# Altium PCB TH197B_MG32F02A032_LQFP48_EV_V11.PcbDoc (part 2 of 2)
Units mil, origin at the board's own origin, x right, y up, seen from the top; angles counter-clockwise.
Board outline 4094.49 x 2637.8 mil, 2 copper layers (Top Layer, Bottom Layer); 114 components, 111 nets, 502 pads, 245 vias.
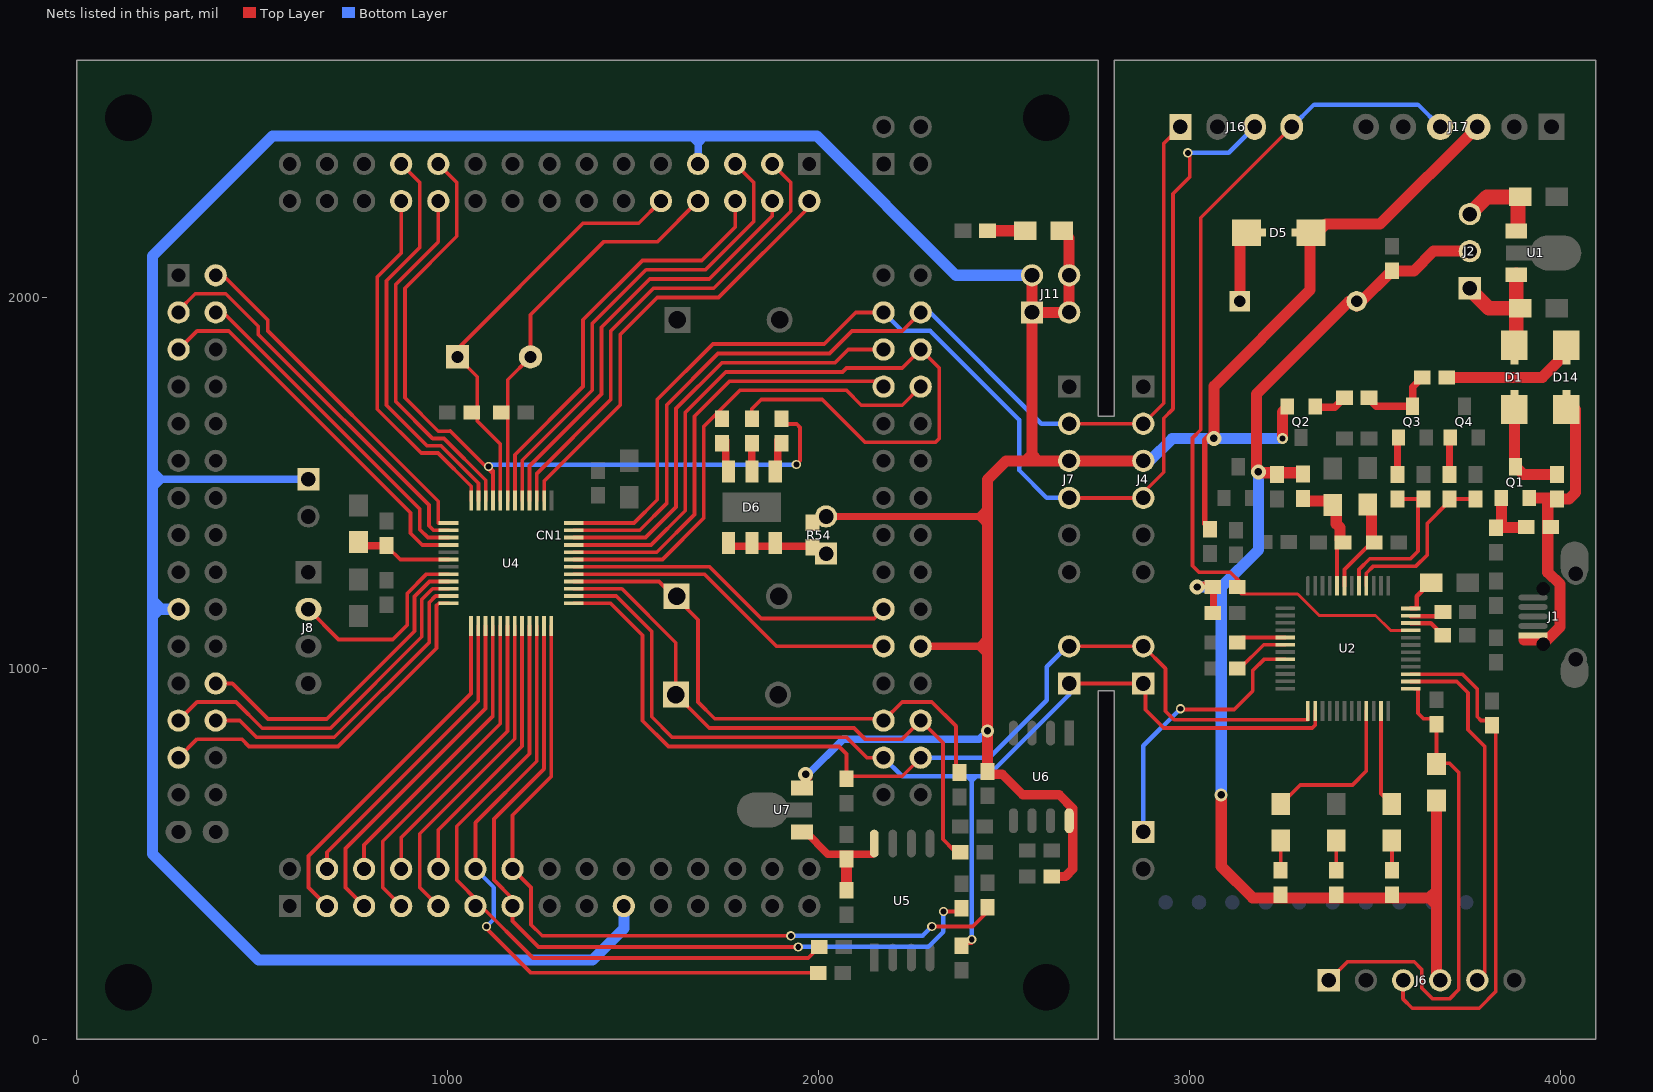
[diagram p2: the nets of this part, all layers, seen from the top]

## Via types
v1: diameter 30, hole 12, Top Layer to Bottom Layer, tented both sides, 93 vias
v2: diameter 20, hole 12, Top Layer to Bottom Layer, tented both sides, 89 vias
v3: diameter 25, hole 12, Top Layer to Bottom Layer, tented both sides, 32 vias
v4: diameter 25, hole 16, Top Layer to Bottom Layer, tented both sides, 21 vias
v5: diameter 40, hole 20, Top Layer to Bottom Layer, tented both sides, 4 vias
v6: diameter 30, hole 16, Top Layer to Bottom Layer, tented both sides, 3 vias
v7: diameter 35, hole 20, Top Layer to Bottom Layer, tented both sides, 2 vias
v8: diameter 50, hole 12, Top Layer to Bottom Layer, tented both sides, 1 vias

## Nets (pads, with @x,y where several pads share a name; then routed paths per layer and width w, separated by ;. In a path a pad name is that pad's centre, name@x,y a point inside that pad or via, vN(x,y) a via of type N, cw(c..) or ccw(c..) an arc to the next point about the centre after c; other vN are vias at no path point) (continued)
ICP/SWD_SDA: J16.4 J17.4 R13.2 U2.33 | length 2401.6
  Top Layer w8: R13.2@3138.04,1199.74 3291.04,1199.74 3349.04,1141.74 3501.04,1141.74 3540.94,1101.84 U2.33@3595.5,1101.84
  Top Layer w10: R13.2@3138.04,1218.74 3138.04,1229.74 3109.04,1258.74 3025.04,1258.74 3007.79,1275.99 3007.79,1620.49 3030.04,1642.74 3030.04,2213.74 J16.4@3275.04,2458.74
  Bottom Layer w12: J16.4@3275.04,2458.74 3335.04,2518.74 3615.04,2518.74 J17.4@3675.04,2458.74
MG_PA0: CN1.114 U4.45 | length 929.8
  Top Layer w10: CN1.114@375.04,958.74 420.04,958.74 515.79,862.99 674.29,862.99 ; 620.04,862.99 674.29,862.99 ; U4.45@1002.56,1233.74 951.52,1233.74 910.98,1193.2 910.98,1099.69 674.29,862.99
MG_PA1: CN1.115 U4.46 | length 1056.6
  Top Layer w10: CN1.115@275.04,858.74 325.04,908.74 430.04,908.74 500.54,838.24 684.54,838.24 ; 620.04,838.24 684.54,838.24 ; U4.46@1002.56,1214.06 959.68,1214.05 930.67,1185.05 930.67,1084.37 684.54,838.24
MG_PA2: CN1.116 U4.47 | length 941.9
  Top Layer w10: CN1.116@375.04,858.74 440.04,858.74 485.29,813.49 694.79,813.49 ; 620.04,813.49 694.79,813.49 ; U4.47@1002.56,1194.37 967.83,1194.37 950.35,1176.89 950.35,1069.06 694.79,813.49
MG_PA3: CN1.117 U4.48 | length 1068.7
  Top Layer w10: CN1.117@275.04,758.74 325.04,808.74 445.04,808.74 465.04,788.74 705.04,788.74 ; 620.04,788.74 705.04,788.74 ; U4.48@1002.56,1174.68 975.98,1174.68 970.04,1168.74 970.04,1053.74 705.04,788.74
MG_PA8: CN1.3 U4.1 | length 957.1
  Top Layer w10: CN1.3@675.04,358.74 625.04,408.74 625.04,493.74 1063.03,931.73 U4.1@1063.03,1113.71
MG_PA9: CN1.4 U4.2 | length 823.8
  Top Layer w10: CN1.4@675.04,458.74 675.04,503.74 1082.72,911.42 U4.2@1082.72,1113.71
MG_PA10: CN1.5 U4.3 | length 932
  Top Layer w10: CN1.5@775.04,358.74 725.04,408.74 725.04,513.74 1102.4,891.1 U4.3@1102.4,1113.71
MG_PA11: CN1.6 U4.4 | length 800.8
  Top Layer w10: CN1.6@775.04,458.74 775.04,523.74 1122.09,870.79 ; 1122.09,868.74 1122.09,870.79 ; U4.4@1122.09,1113.71 1122.09,870.79
MG_PA12: CN1.7 U4.5 | length 916.9
  Top Layer w10: CN1.7@875.04,358.74 825.04,408.74 825.04,533.74 1141.77,850.47 1141.77,878.74 ; 1141.77,868.74 1141.77,878.74 ; U4.5@1141.77,1113.71 1141.77,878.74
MG_PA13: CN1.8 U4.6 | length 773.6
  Top Layer w10: CN1.8@875.04,458.74 875.04,543.74 1161.46,830.16 U4.6@1161.46,1113.71
MG_PA14: CN1.9 U4.7 | length 881.8
  Top Layer w10: CN1.9@975.04,358.74 925.04,408.74 925.04,553.74 1181.14,809.84 U4.7@1181.14,1113.71
MG_PA15: CN1.10 U4.8 | length 748.5
  Top Layer w10: CN1.10@975.04,458.74 975.04,563.74 1200.83,789.53 U4.8@1200.83,1113.71
MG_PB0: CN1.11 R48.1 U4.9 | length 1867.4
  Top Layer w10: CN1.11@1080.04,368.74 1082.54,366.24 1230.04,218.74 1972.04,218.74 R48.1@2002.04,248.74 ; CN1.11@1085.04,368.74 1025.04,428.74 1025.04,573.74 1220.51,769.21 1220.51,888.74 ; 1220.51,868.74 1220.51,888.74 ; U4.9@1220.51,1113.71 1220.51,888.74
MG_PB1: CN1.12 R52.1 U4.10 | length 1876.1
  Top Layer w10: CN1.12@1075.04,458.74 1075.04,583.74 1240.2,748.9 1240.2,888.74 ; v4(1105.04,303.74) 1105.04,298.74 1225.04,178.74 R52.1@1999.04,178.74 ; 1240.2,868.74 1240.2,888.74 ; U4.10@1240.2,1113.71 1240.2,888.74
  Bottom Layer w12: CN1.12@1075.04,458.74 1125.04,408.74 1125.04,323.74 v4(1105.04,303.74)
MG_PB2: CN1.13 R49.1 U4.11 | length 2166.9
  Top Layer w10: CN1.13@1175.04,358.74 1175.04,318.74 1245.04,248.74 v4(1945.04,248.74) ; CN1.13@1175.04,378.74 1125.04,428.74 1125.04,593.74 1259.88,728.58 U4.11@1259.88,1113.71 ; v4(2336.31,344.01) R49.1@2385.04,344.01
  Top Layer w12: R49.1@2385.04,344.01 R49.1@2390.31,344.01
  Bottom Layer w12: v4(1945.04,248.74) 2295.04,248.74 2336.31,290.01 v4(2336.31,344.01)
MG_PB3: CN1.14 R50.1 U4.12 | length 2170.3
  Top Layer w10: CN1.14@1175.04,438.74 CN1.14@1175.04,458.74 ; U4.12@1279.57,1113.71 1279.57,708.27 1175.04,603.74 CN1.14@1175.04,458.74 ; v4(1925.04,278.74) 1255.04,278.74 1225.04,308.74 1225.04,408.74 CN1.14@1175.04,458.74 ; v4(2305.04,303.74) 2415.04,303.74 2455.04,343.74 R50.1@2455.04,355.74
  Bottom Layer w12: v4(1925.04,278.74) 2280.04,278.74 v4(2305.04,303.74)
MG_PB8(TX): CN1.33 J5.2 J15.2 R51.1 U2.13 U4.13 | length 2956.1
  Top Layer w10: U4.13@1340.04,1174.68 1439.09,1174.69 1525.29,1088.49 1525.29,858.49 1595.04,788.74 2055.04,788.74 2075.04,768.74 R51.1@2075.04,708.74 ; R51.1@2075.04,701.74 R51.1@2075.04,708.74 ; CN1.33@2275.04,758.74 2225.04,708.74 R51.1@2075.04,708.74 ; J15.2@2675.04,1058.74 J5.2@2875.04,1058.74 2935.04,998.74 2935.04,883.74 2958.04,860.74 ; 3195.04,860.74 2958.04,860.74 ; U2.13@3318.49,884.39 3318.49,860.74 2958.04,860.74
  Bottom Layer w12: CN1.33@2275.04,758.74 2460.04,758.74 2615.04,913.74 2615.04,1003.74 2670.04,1058.74 J15.2@2675.04,1058.74
MG_PB9(RX): CN1.34 J5.1 J15.1 R53.1 U2.14 U4.14 | length 3078.5
  Top Layer w10: U4.14@1340.04,1194.37 1454.41,1194.37 1550.04,1098.74 1550.04,868.74 1605.04,813.74 2075.04,813.74 2130.04,758.74 CN1.34@2175.04,758.74 ; R53.1@2393.04,258.74 v4@2412.6,258.74 ; J15.1@2675.04,958.74 J5.1@2875.04,958.74 2880.81,952.97 2880.81,887.97 2930.04,838.74 3330.04,838.74 3338.18,846.88 U2.14@3338.18,884.39
  Bottom Layer w12: CN1.34@2175.04,758.74 2225.04,708.74 2400.2,708.74 ; v4(2412.6,268.74) 2412.6,696.34 ; J15.1@2675.04,958.74 2675.04,928.74 2455.04,708.74 2425,708.74 ; 2400.2,708.74 2412.6,708.74 ; 2400.2,708.74 2412.6,696.34 ; 2412.6,696.34 2425,708.74 ; 2412.6,696.34 2412.6,708.74 ; 2412.6,708.74 2425,708.74
MG_PB10: CN1.35 R47.1 SW3.1 U4.15 | length 1595.7
  Top Layer w10: U4.15@1340.04,1214.06 1469.72,1214.06 1615.04,1068.74 SW3.1@1615.04,928.74 1705.04,838.74 2095.04,838.74 2125.04,808.74 2225.04,808.74 CN1.35@2275.04,858.74 ; CN1.35@2285.04,848.74 2335.04,798.74 2335.04,538.74 2365.04,508.74 R47.1@2382.04,508.74
MG_PB11: CN1.36 R46.1 SW4.1 U4.16 | length 1531.9
  Top Layer w10: U4.16@1340.04,1233.74 1570.04,1233.74 SW4.1@1613.64,1190.14 ; SW4.1@1597.24,1208.44 1614.59,1191.09 1675.04,1130.64 1675.04,908.74 1720.04,863.74 2170.04,863.74 CN1.36@2175.04,858.74 2225.04,908.74 2305.04,908.74 2370.04,843.74 2370.04,718.74 R46.1@2370.04,703.74 ; SW4.1@1617.24,1188.74 SW4.1@1617.24,1193.74
MG_PB13: CN1.40 U4.17 | length 915.6
  Top Layer w10: U4.17@1340.04,1253.43 1691.85,1253.43 1886.54,1058.74 CN1.40@2175.04,1058.74
MG_PB14: CN1.42 U4.18 | length 903.1
  Top Layer w10: U4.18@1340.04,1273.11 1705.67,1273.11 1845.04,1133.74 2150.04,1133.74 CN1.42@2175.04,1158.74
MG_PC0: CN1.53 R28.1 U4.19 | length 1360.8
  Top Layer w10: U4.19@1340.04,1292.8 1579.09,1292.8 1690.04,1403.74 1690.04,1650.67 1725.57,1686.2 1788.11,1748.74 1870.04,1748.74 ; 1925.04,1748.74 1870.04,1748.74 ; CN1.53@2275.04,1758.74 2225.04,1708.74 2115.04,1708.74 2075.04,1748.74 1870.04,1748.74
MG_PC1: CN1.54 U4.20 | length 1202.3
  Top Layer w10: U4.20@1340.04,1312.48 1563.78,1312.48 1665.29,1413.99 1665.29,1678.99 1759.79,1773.49 1910.04,1773.49 ; 1925.04,1773.49 1910.04,1773.49 ; CN1.54@2175.04,1758.74 2160.29,1773.49 1910.04,1773.49
MG_PC2: CN1.55 R29.1 U4.21 | length 2313.2
  Top Layer w10: U4.21@1340.04,1332.17 1548.46,1332.17 1640.54,1424.24 1640.54,1689.24 1749.54,1798.24 1775.04,1798.24 ; R29.1@1820.04,1671.74 1820.04,1698.74 1845.04,1723.74 2010.04,1723.74 2125.04,1608.74 2315.04,1608.74 2325.04,1618.74 2325.04,1808.74 CN1.55@2275.04,1858.74 2225.04,1808.74 2075.04,1808.74 2064.54,1798.24 1775.04,1798.24 ; 1925.04,1798.24 1775.04,1798.24
MG_PC3: CN1.56 U4.22 | length 1200.2
  Top Layer w10: U4.22@1340.04,1351.85 1533.15,1351.85 1615.79,1434.49 1615.79,1699.49 1739.29,1822.99 2044.29,1822.99 2080.04,1858.74 CN1.56@2175.04,1858.74
MG_PC8: CN1.62 U4.26 | length 1199.7
  Top Layer w10: U4.26@1260.38,1451.69 1260.38,1504.08 1465.04,1708.74 1465.04,1898.74 1565.04,1998.74 1730.04,1998.74 1975.04,2243.74 CN1.62@1975.04,2258.74
MG_PC9: CN1.63 U4.27 | length 1306.3
  Top Layer w10: U4.27@1240.7,1451.69 1240.7,1524.4 1440.04,1723.74 1440.04,1908.74 1555.04,2023.74 1717.41,2023.74 1925.04,2231.37 1925.04,2308.74 CN1.63@1875.04,2358.74
MG_PC10: CN1.64 U4.28 | length 1171.7
  Top Layer w10: U4.28@1221.01,1451.69 1221.01,1544.71 1415.04,1738.74 1415.04,1918.74 1545.04,2048.74 1705.04,2048.74 1875.04,2218.74 CN1.64@1875.04,2258.74
MG_PC11: CN1.65 U4.29 | length 1279.8
  Top Layer w10: U4.29@1201.33,1451.69 1201.33,1560.03 1390.04,1748.74 1390.04,1928.74 1535.04,2073.74 1695.04,2073.74 1825.04,2203.74 1825.04,2308.74 CN1.65@1775.04,2358.74
MG_PC12: CN1.66 U4.30 | length 1146.6
  Top Layer w10: U4.30@1181.64,1451.69 1181.64,1575.34 1365.04,1758.74 1365.04,1938.74 1525.04,2098.74 1685.04,2098.74 1775.04,2188.74 CN1.66@1775.04,2258.74
MG_PD0: CN1.81 R30.1 U4.33 | length 2121.9
  Top Layer w10: CN1.81@975.04,2358.74 1025.04,2308.74 1025.04,2163.74 885.04,2023.74 885.04,1728.74 975.04,1638.74 1006.94,1638.74 ; 1007.26,1639.06 1106.31,1540.01 1122.59,1523.74 ; v4(1110.04,1543.74) 1122.59,1531.19 1122.59,1523.74 ; U4.33@1122.59,1451.69 1122.59,1523.74 ; R30.1@1900.04,1671.74 1914.04,1657.74 1941.04,1657.74 1950.04,1648.74 1950.04,1558.74 v4(1940.04,1548.74)
  Bottom Layer w12: v4@1110.04,1548.74 v4(1940.04,1548.74)
MG_PD1: CN1.82 U4.34 | length 973
  Top Layer w10: CN1.82@975.04,2258.74 975.04,2148.74 860.29,2033.99 860.29,1718.49 959.72,1619.06 990.4,1619.06 1102.9,1506.56 U4.34@1102.9,1451.69
MG_PD2: CN1.83 U4.35 | length 1089.6
  Top Layer w10: CN1.83@875.04,2358.74 925.04,2308.74 925.04,2133.74 835.54,2044.24 835.54,1708.24 944.41,1599.37 982.25,1599.37 1083.22,1498.4 U4.35@1083.22,1451.69
MG_PD3: CN1.84 U4.36 | length 964.7
  Top Layer w10: CN1.84@875.04,2258.74 875.04,2118.74 810.79,2054.49 810.79,1697.99 929.09,1579.69 974.09,1579.69 1063.53,1490.25 U4.36@1063.53,1451.69
MG_PD7: CN1.92 U4.37 | length 955
  Top Layer w10: CN1.92@375.04,2058.74 395.04,2058.74 515.04,1938.74 515.04,1909.8 975.04,1449.81 975.04,1391.63 975.45,1391.22 U4.37@1002.56,1391.22
MG_PD8: CN1.93 U4.38 | length 1060.4
  Top Layer w10: CN1.93@275.04,1958.74 275.04,1963.74 320.04,2008.74 402.41,2008.74 490.04,1921.11 490.04,1899.45 950.04,1439.45 950.04,1383.74 962.24,1371.54 U4.38@1002.56,1371.54
MG_PD9: CN1.94 U4.39 | length 911.3
  Top Layer w10: CN1.94@375.04,1958.74 395.39,1958.74 500.22,1853.92 925.04,1429.1 925.04,1373.74 946.93,1351.85 U4.39@1002.56,1351.85
MG_PD10: CN1.95 U4.40 | length 1019.3
  Top Layer w10: CN1.95@275.04,1858.74 325.04,1908.74 410.04,1908.74 482.54,1836.24 900.04,1418.74 900.04,1363.74 931.61,1332.17 U4.40@1002.56,1332.17
NetC2_2: C2.2 Q1.1 R5.2 | length 170
  Top Layer w30: R5.2@3825.04,1378.74 R5.2@3840.04,1378.74 ; Q1.1@3840.04,1463.74 Q1.1@3840.04,1458.74 R5.2@3840.04,1378.74 ; C2.2@3910.04,1378.74 3907,1378.74 R5.2@3840.04,1378.74
NetC6_1: C6.1 C7.2 R10.2 U2.44 | length 305.4
  Top Layer w11: U2.44@3397.23,1221.87 C7.2@3397.23,1338.74
  Top Layer w30: R10.2@3320.04,1450.74 3385,1450.74 C6.1@3385,1439.53 3395,1429.53 3395,1388.74 3405,1378.74 3405,1346.78 C7.2@3413.04,1338.74
NetC8_2: C8.2 C9.1 U2.43 | length 256.3
  Top Layer w11: U2.43@3416.92,1221.87 3416.92,1265.62 C8.2@3490.04,1338.74
  Top Layer w30: C9.1@3480,1440.79 3490,1430.79 3490,1345.78 C8.2@3497.04,1338.74
NetC11_1: C11.1 U2.36 | length 103.2
  Top Layer w12: U2.36@3595.5,1160.9 3612.2,1160.9 3612.2,1193.42 3649.42,1230.64 C11.1@3650.79,1230.64
NetC15_1: C15.1 C17.1 U4.42 | length 290.7
  Top Layer w10: C17.1@835.04,1338.74 839.02,1334.76 839.02,1330.74 839.02,1325.98 872.2,1292.8 U4.42@1002.56,1292.8 973.5,1292.8
  Top Layer w20: C15.1@765,1329.53 C17.1@835,1329.53
NetD1_1: D1.1 Q1.3 R1.2 | length 306
  Top Layer w30: D1.1@3875,1697.13 3875,1545.72 3898.98,1521.74 ; Q1.3@3878.04,1542.68 3898.98,1521.74 ; R1.2@3990.04,1521.74 3898.98,1521.74
NetD2_1: D2.1 R6.2 | length 97
  Top Layer w10: R6.2@3245.04,446.74 R6.2@3245.04,455 D2.1@3245.04,535.79 D2.1@3245.04,543.74
NetD3_1: D3.1 R9.2 | length 97
  Top Layer w10: R9.2@3545.04,446.74 R9.2@3545.04,455 D3.1@3545.04,535.79 D3.1@3545.04,543.74
NetD4_1: D4.1 R11.2 | length 97
  Top Layer w10: R11.2@3395.04,446.74 R11.2@3395.04,455 D4.1@3395.04,535.79 D4.1@3395.04,543.74
NetD5_1: D5.1 SW1.1 | length 215.1
  Top Layer w20: D5.1@3135.87,2173.74 D5.1@3153.39,2173.74 D5.1@3186.85,2173.74
  Top Layer w30: SW1.1@3135.08,1988.74 D5.1@3135.08,2152.87
NetD6_1: D6.1 D6.3 D6.5 R54.1 | length 210
  Top Layer w20: D6.1@1760,1328.74 1820.04,1328.74 1883.03,1328.74 R54.1@1970,1328.74
NetD6_2: D6.2 R28.2 | length 83.5
  Top Layer w20: D6.2@1750.04,1530.2 1750.04,1605.74 R28.2@1750.04,1613.74
NetD6_4: D6.4 R29.2 | length 75.5
  Top Layer w20: D6.4@1820.04,1530.2 R29.2@1820.04,1605.74
NetD6_6: D6.6 R30.2 | length 83.5
  Top Layer w20: D6.6@1890.04,1530.2 1890.04,1605.74 R30.2@1890.04,1613.74
NetD7_2: D7.2 R31.2 | length 101.6
  Top Layer w30: R31.2@2455.04,2178.74 D7.2@2556.61,2178.74
NetD14_2: D14.2 R17.1 | length 348.7
  Top Layer w30: R17.1@3693,1783.74 3945,1783.74 ; 3950,1783.74 D14.2@4009.08,1842.81 ; D14.2@3998.15,1866.89 D14.2@4010,1866.89 ; D14.2@4004.08,1842.81 D14.2@4005,1843.74
NetQ2_1: Q2.1 R18.2 | length 89.8
  Top Layer w20: Q2.1@3338,1702.68 3390.98,1702.68 R18.2@3417.04,1728.74
NetQ3_1: Q3.1 R19.2 | length 117.1
  Top Layer w20: R19.2@3560.04,1538.78 R19.2@3560.04,1521.74 Q3.1@3560.04,1619.27 ; Q3.1@3562.54,1619.27 Q3.1@3562.54,1621.77
NetQ3_2: Q3.2 R17.2 R18.1 | length 192.7
  Top Layer w20: R18.1@3488.04,1728.74 3488.04,1720.7 3503.03,1705.71 Q3.2@3600.54,1705.71 ; 3600.54,1728.74 3600.54,1757.28 R17.2@3627,1783.74
NetQ4_1: Q4.1 R23.2 | length 100
  Top Layer w20: R23.2@3700.04,1521.74 Q4.1@3700.04,1619.27 ; Q4.1@3702.54,1619.27 Q4.1@3702.54,1621.77
NetR15_1: R15.1 U2.35 | length 108.8
  Top Layer w12: U2.35@3595.5,1140.21 3625.04,1140.21 ; 3657.3,1140.21 3625.04,1140.21 ; R15.1@3672.04,1140.21 3625.04,1140.21
NetR16_1: R16.1 U2.34 | length 100.1
  Top Layer w12: U2.34@3595.5,1121.53 3649.25,1121.53 R16.1@3682.04,1088.74
ONBOARD_ICP/SWD_SCL: CN1.57 J4.2 J7.2 J16.1 U4.23 | length 2927.6
  Top Layer w10: U4.23@1340.04,1371.54 1517.83,1371.54 1591.04,1444.75 1591.04,1709.75 1729.03,1847.74 1915.04,1847.74 ; 1925.04,1847.74 1915.04,1847.74 ; CN1.57@2275.04,1958.74 2225.04,1908.74 2090.04,1908.74 2029.03,1847.74 1915.04,1847.74 ; J7.2@2675.04,1658.74 J4.2@2875.04,1658.74 ; J4.2@2875.04,1652.74 2878.04,1655.74 J4.2@2881.04,1658.74 ; J4.2@2885.04,1658.74 J4.2@2881.04,1658.74 ; J16.1@2975.04,2458.74 2930.04,2413.74 2930.04,1713.74 J4.2@2875.04,1658.74 ; J4.2@2875.04,1658.74 J4.2@2881.04,1658.74
  Bottom Layer w12: CN1.57@2275.04,1958.74 2300.04,1958.74 2600.04,1658.74 J7.2@2675.04,1658.74
ONBOARD_ICP/SWD_SDA: CN1.58 J4.4 J7.4 J16.3 U4.24 | length 3438
  Top Layer w10: U4.24@1340.04,1391.22 1502.52,1391.22 1565.04,1453.74 1565.04,1723.74 1715.04,1873.74 2015.04,1873.74 2100.04,1958.74 CN1.58@2175.04,1958.74 ; J7.4@2675.04,1458.74 J4.4@2860.04,1458.74 ; J4.4@2867.54,1465.24 2868.04,1465.74 2930.04,1527.74 2930.04,1673.74 2955.04,1698.74 2955.04,2278.74 3000.04,2323.74 v4@3000.04,2388.74 ; J4.4@2867.54,1471.24 2867.54,1466.24 J4.4@2860.04,1458.74 ; J4.4@2875.04,1458.74 J4.4@2860.04,1458.74
  Bottom Layer w12: CN1.58@2195.04,1958.74 CN1.58@2175.04,1958.74 2225.04,1908.74 2301,1908.74 2540.04,1669.7 2540.04,1533.74 2615.04,1458.74 J7.4@2675.04,1458.74 ; v4(2995.04,2388.74) 3105.04,2388.74 J16.3@3175.04,2458.74
P44: J6.5 U2.26 | length 969
  Top Layer w10: U2.26@3595.5,964.05 3719.73,964.05 3750.04,933.74 3750.04,833.74 3795.04,788.74 3795.04,178.74 J6.5@3775.04,158.74
P45: J6.3 R25.1 U2.27 | length 1341.2
  Top Layer w10: J6.3@3575.04,158.74 3575.04,108.74 3600.04,83.74 3780.04,83.74 3825.04,128.74 R25.1@3825.04,838.74 ; U2.27@3595.5,983.73 3735.05,983.73 3775.04,943.74 3775.04,868.74 3785.04,858.74 R25.1@3802.04,858.74
PASS: D3.2 U2.23 | length 264.5
  Top Layer w10: U2.23@3515.34,884.39 3515.34,661.86 3544.02,633.19 D3.2@3545.04,632.17
RST: C12.2 J6.1 R22.2 U2.25 | length 1359.8
  Top Layer w10: J6.1@3375.04,158.74 3425.04,208.74 3605.04,208.74 3625.04,188.74 3625.04,138.74 3655.04,108.74 3700.04,108.74 3725.04,133.74 3725.04,718.7 3700,743.74 3680.04,743.74 3673.43,750.35 C12.2@3665.04,758.74 ; U2.25@3605.04,944.36 3614.42,944.36 3615.04,943.74 3615.04,878.74 3630.04,863.74 3665.04,863.74 R22.2@3665.04,848.74 C12.2@3665.04,758.74 ; C12.2@3665.04,748.74 C12.2@3665.04,758.74
RST_CTRL_51: R19.1 R20.1 U2.41 | length 433.9
  Top Layer w10: U2.41@3456.29,1221.87 3456.29,1265.99 3485.3,1295 3595,1295 3615.04,1315.04 R20.1@3615.04,1455.74 ; R19.1@3560.04,1455.74 R20.1@3615.04,1455.74 ; R20.1@3630.04,1455.74 R20.1@3615.04,1455.74
RST_CTRL_ARM: R23.1 R24.1 U2.40 | length 454.6
  Top Layer w10: U2.40@3475.97,1221.87 3475.97,1255.67 3495.3,1275 3610,1275 3640.04,1305.04 3640.04,1390.04 R23.1@3697.5,1447.5 ; R23.1@3700.04,1455.74 R24.1@3770.04,1455.74
TOOL_OPTION0: R2.1 U2.5 | length 210.8
  Top Layer w10: R2.1@3128.04,1068.74 3141.96,1082.66 U2.5@3257.52,1082.66 3181.96,1082.66
TOOL_OPTION1: R3.1 U2.6 | length 156.1
  Top Layer w10: R3.1@3128.04,998.74 3135.04,998.74 3199.27,1062.97 U2.6@3257.52,1062.97
USBOK: D2.2 U2.21 | length 430.2
  Top Layer w10: D2.2@3245.04,632.17 3246.06,633.19 3297.87,685 3438.46,685 3475.97,722.51 U2.21@3475.97,884.39
VCC3: C20.1 R32.2 U5.8 U7.1 | length 317.5
  Top Layer w20: U7.1@1945.04,558.74 U7.1@1955.04,558.74 1965.04,558.74 2025.04,498.74 2075.04,498.74 2145.04,498.74 2150.04,503.74 U5.8@2150.04,522.28
  Top Layer w30: R32.2@2075.04,408.74 C20.1@2075.04,475.74
VCC_USB: C2.1 D14.1 J1.1 Q1.2 R1.1 | length 798.6
  Top Layer w30: 3901.69,1076.22 3925.04,1076.22 3952.6,1076.22 3962.48,1076.22 3997.48,1111.22 3997.48,1226.22 3967.48,1256.22 ; Q1.2@3915.04,1458.74 3967.04,1458.74 ; 3964.92,1257.56 3964.92,1380 3964.92,1445.62 ; R1.1@3980.04,1455.74 R1.1@3990.04,1455.74 4022,1455.74 4040,1473.74 D14.1@4040,1697.13
VCP_OPTION: J3.1 U2.8 | length 743.9
  Top Layer w10: v4@2975.04,888.74 3120.04,888.74 3170.04,938.74 3170.04,993.74 3199.9,1023.6 U2.8@3257.52,1023.6
  Bottom Layer w12: J3.1@2875.04,558.74 2875.04,790.64 v4(2975.04,890.64)
VDD: C12.1 J2.2 J6.4 R4.1 R6.1 R9.1 R10.1 R11.1 R12.1 R13.1 R14.2 SW1.2 | length 3508.3
  Top Layer w11: 3633.04,380.74 3655.04,358.74 ; 3640.04,388.74 3658.04,406.74
  Top Layer w20: v5@3028.11,1223.74 R13.1@3062.04,1223.74 ; R12.1@3064.04,1148.74 R13.1@3064.04,1218.3
  Top Layer w30: v7@3085.04,658.74 3085.04,465.7 3170,380.74 3245.04,380.74 3395.04,380.74 3545.04,380.74 3633.04,380.74 3658.04,380.74 ; R14.2@3240,1526.74 3235,1526.74 3187,1526.74 v5(3185,1528.74) 3180,1533.74 3180,1738.74 3428.75,1987.49 3438.83,1987.49 3443.81,1982.51 3450.04,1976.28 3456.27,1982.51 3544.5,2070.74 R4.1@3545.04,2070.74 3604,2070.74 3657,2123.74 J2.2@3755.04,2123.74 ; R14.2@3245,1526.74 R10.1@3305,1526.74 ; C12.1@3665.04,643.53 3665.04,168.74 J6.4@3675.04,158.74 J6.4@3675.04,168.74
  Bottom Layer w30: v5(3020.04,1218.74) 3085.04,1218.74 ; v7@3085.04,658.74 3085.04,1218.74 ; v5(3185,1528.74) 3185,1318.7 3085.04,1218.74
  other v7: 3084.94,658.74
VDD3: C5.1 J2.3 U1.1 | length 231.2
  Top Layer w40: J2.3@3755.04,2223.74 3801.3,2270 C5.1@3885,2270 ; U1.1@3885,2193.74 C5.1@3885,2270 ; C5.1@3890.79,2270 C5.1@3885,2270
VDD5: C4.1 D1.2 J2.1 U1.3 | length 318.5
  Top Layer w40: J2.1@3753.56,2022.26 3805.83,1970 C4.1@3880,1970 ; D1.2@3880,1900.35 C4.1@3880,1970 ; U1.3@3880,2060 C4.1@3880,1970 ; C4.1@3890.79,1970 C4.1@3880,1970
VDUT: CN1.19 CN1.39 CN1.67 CN1.109 D5.2 D7.1 J4.3 J7.3 J11.1 J11.2 J11.3 J11.4 J17.3 J18.1 Q2.2 R7.1 R44.1 R45.1 R54.2 U6.8 U7.3 | length 12451.3
  Top Layer w11: 2445.04,1388.74 2425.04,1408.74 2445.04,1428.74 ; 2455.04,1028.74 2425.04,1058.74 2455.04,1088.74 ; 2550.04,1563.74 2575.04,1588.74 2605.04,1558.74
  Top Layer w15: R7.1@3055.04,1374.74 3040.04,1389.74 3040.04,1614.24 3055.04,1629.24 3065.04,1639.24 ; v5@3072.79,1611.49 v5@3075.04,1613.74
  Top Layer w20: U7.3@1945.04,676.85 1950.04,681.85 v5@1973.48,705.3 ; R54.2@2020,1408.74 2425.04,1408.74 2455.04,1408.74 ; CN1.39@2275.04,1058.74 2425.04,1058.74 2455.04,1058.74 ; D5.2@3293.15,2173.74 D5.2@3326.61,2173.74 D5.2@3344.13,2173.74
  Top Layer w25: R44.1@2455.04,713.74 2495.04,713.74 2550.04,658.74 2648.15,658.74 2685.04,621.85 2685.04,588.74 2685.04,458.74 2665.04,438.74 R45.1@2628.04,438.74
  Top Layer w30: R44.1@2455.04,731.74 v7(2455.04,830.74) 2455.04,1028.74 2455.04,1058.74 2455.04,1088.74 2455.04,1408.74 2455.04,1508.74 2505.04,1558.74 2575.04,1558.74 ; J11.2@2575.04,2058.74 J11.1@2575.04,1958.74 ; D7.1@2675.04,2158.74 J11.4@2675.04,2058.74 J11.3@2675.04,1958.74 J11.1@2575.04,1958.74 ; J4.3@2875.04,1558.74 J7.3@2675.04,1558.74 2605.04,1558.74 2575.04,1558.74 ; v5(3065.04,1619.24) 3065.04,1639.24 3065.04,1759.65 3324.13,2018.74 D5.2@3324.13,2168.74 ; v6@3250,1619.24 3250,1689.68 Q2.2@3263,1702.68 ; D5.2@3339.13,2168.74 3344.13,2173.74 3366.89,2196.5 3512.8,2196.5 J17.3@3775.04,2458.74 ; 2575.04,1558.74 2575.04,1588.74 J11.1@2575.04,1958.74
  Bottom Layer w20: 205.04,1133.78 230,1158.74 ; 205.04,1188.74 235.04,1158.74 ; 205.04,1508.74 230,1508.74 ; 205.04,1533.7 230,1508.74 ; 209.96,1488.7 230,1508.74 ; J18.1@625.04,1508.74 230,1508.74 ; 1655.04,2433.74 1675.04,2413.74 ; CN1.67@1675.04,2358.74 1675.04,2413.74 ; 1675.04,2428.74 1675.04,2413.74 ; 1695.04,2433.74 1675.04,2413.74 ; v5@1971.29,713.74 2066.29,808.74 2433.04,808.74 v7(2455.04,830.74)
  Bottom Layer w30: CN1.109@275.04,1158.74 235.04,1158.74 230,1158.74 205.04,1158.74 ; CN1.19@1475.04,358.74 1475.04,298.74 1390.04,213.74 490.75,213.74 205.04,499.45 205.04,1133.78 205.04,1158.74 ; J11.2@2575.04,2058.74 2370.04,2058.74 1995.04,2433.74 1695.04,2433.74 1655.04,2433.74 528.23,2433.74 205.04,2110.55 205.04,1533.7 205.04,1508.74 205.04,1188.74 205.04,1158.74 ; J4.3@2893.07,1559.24 2953.07,1619.24 v5(3065.04,1619.24) v6@3250,1619.24
  other v5: 1965.04,713.74
  other v6: 3250,1618.74
VREF+: J8.2 U4.44 | length 533.8
  Top Layer w10: J8.2@625.04,1158.74 706.3,1077.48 852.42,1077.48 891.3,1116.36 891.3,1201.36 943.37,1253.43 U4.44@1002.56,1253.43
XIN/MG_PC13: C19.1 CN1.68 U4.31 X1.2 | length 1104.5
  Top Layer w10: U4.31@1161.96,1451.69 1161.96,1688.74 1161.96,1777.23 X1.2@1223.46,1838.74 1223.46,1952.17 1420.04,2148.74 1565.04,2148.74 CN1.68@1675.04,2258.74
XOUT/MG_PC14: C18.1 CN1.70 U4.32 X1.1 | length 1170
  Top Layer w10: U4.32@1142.27,1451.69 1142.27,1603.95 1080.04,1666.18 1080.04,1688.74 1080.04,1785.32 X1.1@1026.61,1838.74 1026.61,1860.32 1365.04,2198.74 1515.04,2198.74 CN1.70@1575.04,2258.74
pads on no net: CN1.1 CN1.2 CN1.15 CN1.16 CN1.18 CN1.20 CN1.21 CN1.22 CN1.23 CN1.24 CN1.25 CN1.26 CN1.27 CN1.28 CN1.29 CN1.30 CN1.31 CN1.32 CN1.37 CN1.38 CN1.43 CN1.44 CN1.45 CN1.46 CN1.47 CN1.48 CN1.49 CN1.50 CN1.51 CN1.52 CN1.60 CN1.61 CN1.71 CN1.72 CN1.73 CN1.74 CN1.75 CN1.76 CN1.77 CN1.78 CN1.79 CN1.80 CN1.85 CN1.86 CN1.87 CN1.88 CN1.89 CN1.90 CN1.91 CN1.96 CN1.97 CN1.98 CN1.99 CN1.100 CN1.101 CN1.102 CN1.103 CN1.104 CN1.105 CN1.106 CN1.108 CN1.110 CN1.111 CN1.112 CN1.113 CN1.118 CN1.119 CN1.120 CN1.121 CN1.122 D6.0 J1.0 J6.6 J7.1 J8.4 U2.1 U2.2 U2.3 U2.4 U2.7 U2.24 U2.28 U2.29 U2.30 U2.32 U2.37 U2.38 U2.39 U2.46

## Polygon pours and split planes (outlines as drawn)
GND_POWER on Bottom Layer "Top Layer-No Net" (hatched 90Degree grid 10 track 10, remove dead copper, pour order 1001): 25,20 4070,20 4070,2593.74 25,2593.74
GND_POWER on Top Layer "Top Layer-No Net" (hatched 90Degree grid 10 track 10, remove dead copper, pour order 1001): 25,20 4070,20 4070,2593.74 25,2593.74

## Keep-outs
Keep-Out Layer:
  circle w7.88: c140,140 r133.86
  circle w7.88: c2613.39,140 r133.86
  circle w7.88: c2613.39,2483.43 r133.86
  circle w7.88: c140,2483.43 r133.86
  lines w15: 0,0 0,2637.8 2753.39,2637.8 2753.39,1678.74 2796.69,1678.74 2796.69,2637.8 4094.49,2637.8 4094.49,0 2796.69,0 2796.69,938.74 2753.39,938.74 2753.39,0 0,0

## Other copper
Top Layer:
  pour cut-out: 2710,2623.74 2830,2623.74 2830,0 2710,0
Bottom Layer:
  pour cut-out: 2710,2520 2830,2520 2830,0 2710,0

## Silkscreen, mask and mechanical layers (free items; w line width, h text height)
Top Overlay:
  circle w10: c140,140 r137.8
  circle w4: c2613.39,140 r137.8
  circle w10: c2613.39,2483.43 r137.8
  circle w10: c140,2483.43 r137.8
  lines w8: 505.04,1160.64 566.94,1160.64 ; 547.04,1145.64 566.94,1160.64 ; 547.04,1175.64 566.94,1160.64
  text "PD2" at 895.04,2423.74 h50 r90
  text "PD0" at 995.04,2423.74 h50 r90
  text "GND" at 1595.04,2423.74 h50 r90
  text "VDUT" at 1695.04,2423.74 h50 r90
  text "PC11" at 1795.04,2423.74 h50 r90
  text "PC9" at 1895.04,2423.74 h50 r90
  text "When J16 Open," at 2840.04,2333.74 h45
  text "SCL" at 3895.04,2318.74 h35 r90
  text "CLK" at 3995.04,2318.74 h35 r90
  text "RST" at 3495.04,2308.74 h37 r90
  text "GND" at 3595.04,2303.74 h37 r90
  text "SDA" at 3695.04,2303.74 h37 r90
  text "VCC" at 3795.04,2303.74 h37 r90
  text "SW1 must be off." at 2840.04,2258.74 h45
  text "GND" at 2149.94,2238.74 h50
  text "Power" at 2515.04,2238.74 h50
  text "VDD3" at 3565,2200.64 h37
  text "VDD" at 3595.04,2103.74 h37
  text "PD3" at 895.04,2063.74 h50 r90
  text "PD1" at 995.04,2063.74 h50 r90
  text "PC8" at 1995.04,2063.74 h50 r90
  text "PC6" at 2340.04,2038.74 h50
  text "PD7" at 445.04,2028.74 h50
  text "PC14" at 1605.04,2023.74 h50 r90
  text "PC13" at 1695.04,2023.74 h50 r90
  text "PC12" at 1795.04,2023.74 h50 r90
  text "PC10" at 1895.04,2023.74 h50 r90
  text "VDD5" at 3565,1990.64 h37
  text "PD8" at 85.04,1938.74 h50
  text "PC5" at 1970.04,1938.74 h50
  text "PC4" at 2340.04,1938.74 h50
  text "PD9" at 445.04,1928.74 h50
  text "Power On" at 3375.04,1843.74 h45
  text "VDUT" at 2515.04,1840.64 h50
  text "PD10" at 49.92,1838.74 h50
  text "PC3" at 1970.04,1838.74 h50
  text "PC2" at 2340.04,1838.74 h50
  text "Power Off" at 2945.04,1838.74 h45
  text "RESET" at 1559.94,1760 h50 r90
  text "PC1" at 1985.04,1738.74 h50
  text "PC0" at 2338.34,1733.74 h50
  text "SCL" at 2530.04,1643.74 h33
  text "U4 current" at 476.68,1632.55 h50
  text "measurement" at 476.59,1571.08 h50
  text "VDUT" at 2495.04,1538.74 h33
  text "SDA" at 2525.04,1443.74 h33
  text "GND" at 2525.04,1338.74 h33
  text "RST" at 2530.04,1238.74 h33
  text "GND" at 85.04,1228.74 h50
  text "VDD" at 565.04,1200.64 h50 r90
  text "PB11" at 1565,1140.64 h50 r90
  text "PB14" at 1930.04,1138.74 h50
  text "GND" at 2340.04,1138.74 h50
  text "VDUT" at 45,1130.64 h50
  text "PB8_TX" at 2487.04,1113.74 h38
  text "VREF" at 500.04,1090.64 h50 r90
  text "↓" at 2995.04,1058.74 h100 r90
  text "PB13" at 1930.04,1038.74 h50
  text "↓" at 2605.04,1038.74 h100 r90
  text "VDUT" at 2340.04,1033.74 h50
  text "GND" at 565.04,1000.64 h50 r90
  text "↓" at 2555.04,978.74 h100 r270
  text "↓" at 2945.04,958.74 h100 r270
  text "PA0" at 439.94,933.74 h50
  text "PB9_RX" at 2423.04,908.74 h38
  text "PB10" at 1565,860.64 h50 r90
  text "PB11" at 1945.04,838.74 h50
  text "PB10" at 2340.04,838.74 h50
  text "PA2" at 440.04,830.64 h50
  text "PA1" at 95.04,828.74 h50
  text "TH197B_MG32F02A032" at 709.94,823.74 h45
  text "PB8" at 2340.04,763.74 h50
  text "PB9" at 1965.04,748.74 h50
  text "LQFP48_EV_V11" at 725,740 h45
  text "2021.05" at 1319.94,733.74 h38
  text "PA3" at 75.04,728.74 h50
  text "PA9" at 695.04,523.74 h50 r90
  text "PA11" at 795.04,523.74 h50 r90
  text "PA13" at 895.04,523.74 h50 r90
  text "PA15" at 995.04,523.74 h50 r90
  text "PB1" at 1100.04,523.74 h50 r90
  text "PB3" at 1195.04,523.74 h50 r90
  text "J3 Open : Disable VCP." at 2828.04,298.74 h45
  text "J3 Short : Enable VCP." at 2823.04,223.74 h45
  text "PB0" at 1100.04,168.74 h50 r90
  text "GND" at 1405.04,168.74 h50 r90
  text "PA8" at 695.04,163.74 h50 r90
  text "PB2" at 1195.04,163.74 h50 r90
  text "VDUT" at 1500.04,124.45 h50 r90
  text "PA10" at 795.04,123.74 h50 r90
  text "PA12" at 895.04,123.74 h50 r90
  text "PA14" at 995.04,123.74 h50 r90
Mechanical 1:
  circle w7.88: c2775.04,1613.74 r27
  circle w7.88: c2775.04,1503.74 r27
  circle w7.88: c2775.04,1416.74 r25
  circle w7.88: c2775.04,1298.74 r25
  circle w7.88: c2775.04,1008.74 r33
  lines w7.88: 2753.39,1078.74 2753.39,1232.74 2796.69,1232.74 2796.69,1078.74 2753.39,1078.74
  lines w8.88: 0,0 0,2637.8 2753.39,2637.8 2753.39,1678.74 2796.69,1678.74 2796.69,2637.8 4094.49,2637.8 4094.49,0 2796.69,0 2796.69,938.74 2753.39,938.74 2753.39,0 0,0
Mechanical 2:
  lines w6: 2775.04,1031.74 2775.04,1008.74 2798.04,1008.74 ; 2775.04,1321.74 2775.04,1298.74 2798.04,1298.74 ; 2775.04,1441.74 2775.04,1418.74 2798.04,1418.74 ; 2775.04,1526.74 2775.04,1503.74 2798.04,1503.74 ; 2775.04,1636.74 2775.04,1613.74 2798.04,1613.74
Drill Drawing:
  text ".Legend" at 4175,15 h40

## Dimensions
0,0 to 0,2637.8 on Top Overlay
0,0 to 4094.49,0 on Top Overlay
